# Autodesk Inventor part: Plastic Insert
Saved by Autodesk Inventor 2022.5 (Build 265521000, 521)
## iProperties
Created: 2024-07
Part Number: Plastic Insert
Material: Generic
Document SubType Name: Modeling
Designer: AdminForWorker
Density: 1 g/cm^3
Appearance: Default
Title: Plastic Insert
Author: AdminForWorker
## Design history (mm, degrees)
feature "Plastic Insert"
body "Solid1"
